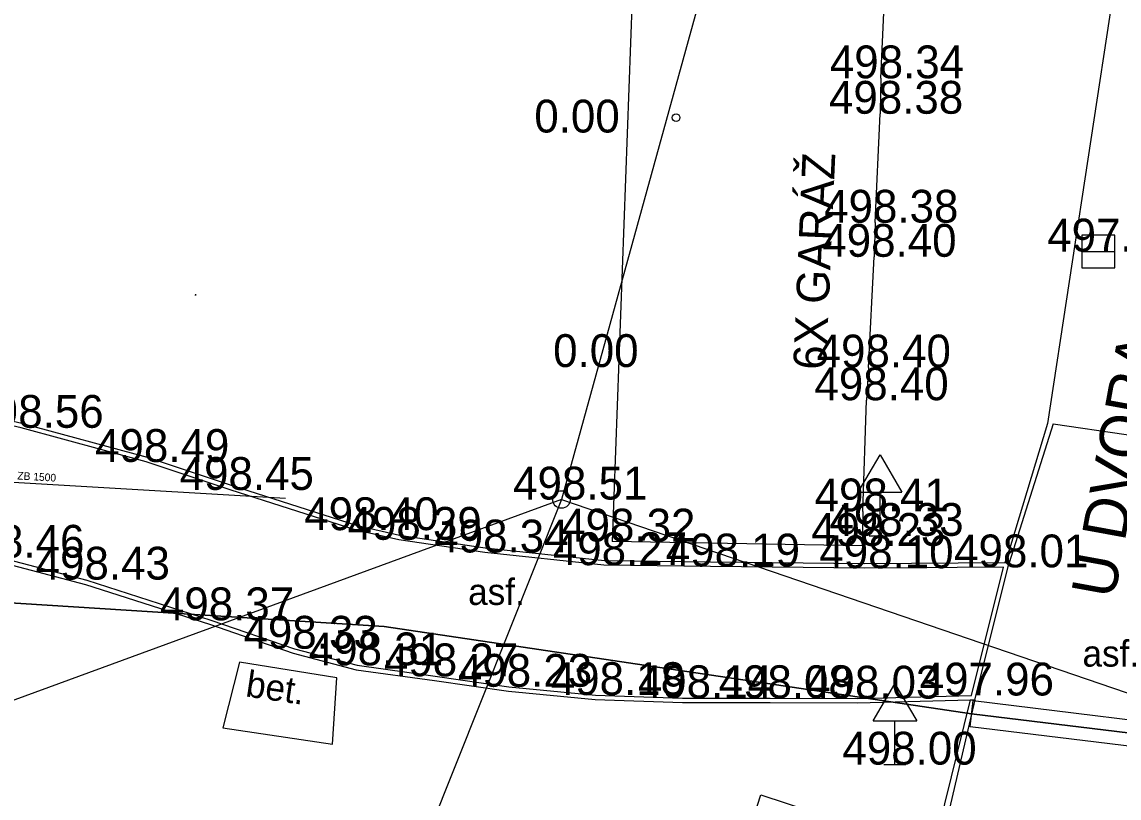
# Model space of a CAD drawing. Extents: x -669642 to -669119, y -1131006 to -1130466.
# Drawn here: x -669595.35 to -669570.28, y -1130617.18 to -1130599.43 of the extents above; entities that cross this region are included whole.
import ezdxf

# ---------------------------------------------------------------- set-up
doc = ezdxf.new("R2010")
doc.units = 0
for name, color, linetype in [('G_Bod_tecka', 7, 'Continuous'), ('G_Bod_vyska', 7, 'Continuous'), ('G_Budovy-znacky', 7, 'Continuous'), ('G_Budovy_Objekty', 7, 'Continuous'), ('G_Budovy_vstupy', 7, 'Continuous'), ('G_Cesty_Schody', 7, 'Continuous'), ('G_Objekty_dopravni', 7, 'Continuous'), ('G_Plochy_zpevnene', 7, 'Continuous'), ('G_Popisy_Nazvy', 7, 'Continuous'), ('G_Popisy_objektu', 7, 'Continuous'), ('G_Popisy_povrchu', 7, 'Continuous'), ('G_Site-kanalizace', 7, 'Continuous'), ('G_Site-Sloupy', 7, 'Continuous'), ('G_Vyskopis-bod_terenu', 7, 'Continuous'), ('G_Z_CHRANICKA-TEPLOVOD_kotovane', 7, 'Continuous'), ('G_Z_ELsilove_podz_kotovane', 7, 'Continuous'), ('G_Z_KANAL_podz_priblizne', 7, 'Continuous'), ('G_Z_SPOJE_nadz_kotovane', 7, 'Continuous'), ('G_Z_SPOJE_podz_kotovane', 7, 'Continuous'), ('Vrstva 17', 7, 'Continuous'), ('Vrstva 3', 7, 'Continuous')]:
    doc.layers.add(name, color=color, linetype=linetype)

msp = doc.modelspace()

# ---------------------------------------------------------------- linework, layer by layer
at = {"layer": 'G_Bod_tecka'}
for p, q in [((-669575.72, -1130600.72), (-669575.72, -1130600.72)), ((-669575.74, -1130601.53), (-669575.74, -1130601.53)), ((-669582.86, -1130601.96), (-669582.86, -1130601.96)), ((-669575.85, -1130604.02), (-669575.85, -1130604.02)), ((-669570.75, -1130604.68), (-669570.75, -1130604.68)), ((-669575.87, -1130604.8), (-669575.87, -1130604.8)), ((-669582.43, -1130607.32), (-669582.43, -1130607.32)), ((-669576, -1130607.33), (-669576, -1130607.33)), ((-669576.05, -1130608.08), (-669576.05, -1130608.08)), ((-669592.51, -1130609.49), (-669592.51, -1130609.49)), ((-669590.59, -1130610.13), (-669590.59, -1130610.13)), ((-669583.02, -1130610.35), (-669583.02, -1130610.35)), ((-669576.13, -1130610.62), (-669576.13, -1130610.62)), ((-669587.72, -1130611.05), (-669587.72, -1130611.05)), ((-669575.74, -1130611.18), (-669575.74, -1130611.18)), ((-669586.74, -1130611.27), (-669586.74, -1130611.27)), ((-669581.86, -1130611.31), (-669581.86, -1130611.31)), ((-669576.15, -1130611.41), (-669576.15, -1130611.41)), ((-669584.77, -1130611.56), (-669584.77, -1130611.56)), ((-669582.05, -1130611.85), (-669582.05, -1130611.85)), ((-669579.61, -1130611.88), (-669579.61, -1130611.88)), ((-669576.09, -1130611.92), (-669576.09, -1130611.92)), ((-669572.92, -1130611.9), (-669572.92, -1130611.9)), ((-669593.87, -1130612.18), (-669593.87, -1130612.18)), ((-669591.03, -1130613.11), (-669591.03, -1130613.11)), ((-669589.12, -1130613.76), (-669589.12, -1130613.76)), ((-669587.68, -1130614.14), (-669587.68, -1130614.14)), ((-669585.91, -1130614.39), (-669585.91, -1130614.39)), ((-669584.22, -1130614.63), (-669584.22, -1130614.63)), ((-669582.24, -1130614.82), (-669582.24, -1130614.82)), ((-669580.25, -1130614.89), (-669580.25, -1130614.89)), ((-669578.24, -1130614.89), (-669578.24, -1130614.89)), ((-669576.24, -1130614.9), (-669576.24, -1130614.9)), ((-669573.65, -1130614.83), (-669573.65, -1130614.83)), ((-669575.4, -1130616.41), (-669575.4, -1130616.41))]:
    msp.add_line(p, q, dxfattribs=at)
at = {"layer": 'G_Budovy-znacky'}
msp.add_circle((-669580.4, -1130601.62), 0.0875, dxfattribs=at)
at = {"layer": 'G_Budovy_Objekty'}
for p, q in [((-669581.1, -1130590.63), (-669581.86, -1130611.31)), ((-669575.72, -1130600.72), (-669575.74, -1130601.53)), ((-669575.85, -1130604.02), (-669575.87, -1130604.8)), ((-669576, -1130607.33), (-669576.05, -1130608.08)), ((-669576.13, -1130610.62), (-669576.15, -1130611.41)), ((-669576.15, -1130611.41), (-669581.86, -1130611.31))]:
    msp.add_line(p, q, dxfattribs=at)
at = {"layer": 'G_Budovy_vstupy'}
for points in [[(-669575.72, -1130600.72), (-669575.61, -1130598.22)], [(-669575.85, -1130604.02), (-669575.74, -1130601.53)], [(-669576, -1130607.33), (-669575.87, -1130604.8)], [(-669576.13, -1130610.62), (-669576.05, -1130608.08)]]:
    msp.add_lwpolyline(points, dxfattribs=at)
at = {"layer": 'G_Cesty_Schody'}
msp.add_line((-669571.78, -1130608.62), (-669572.79, -1130611.8), dxfattribs=at)
for points in [[(-669572.92, -1130611.9), (-669576.09, -1130611.92), (-669579.61, -1130611.88), (-669582.05, -1130611.85), (-669584.77, -1130611.56), (-669586.74, -1130611.27), (-669587.71, -1130611.05), (-669590.59, -1130610.13), (-669592.51, -1130609.49), (-669595.37, -1130608.71), (-669597.32, -1130608.26), (-669599.3, -1130608), (-669601.3, -1130607.84), (-669602.28, -1130607.79)], [(-669571.78, -1130608.62), (-669566.78, -1130609.35)], [(-669604.75, -1130610.71), (-669600.76, -1130610.87), (-669598.76, -1130611.07), (-669595.81, -1130611.68), (-669593.87, -1130612.19), (-669591.03, -1130613.11), (-669589.12, -1130613.76), (-669587.69, -1130614.14), (-669585.91, -1130614.39), (-669584.22, -1130614.63), (-669582.24, -1130614.82), (-669580.25, -1130614.89), (-669578.25, -1130614.89), (-669576.25, -1130614.9)], [(-669576.25, -1130614.9), (-669573.65, -1130614.83), (-669572.92, -1130611.9)], [(-669573.57, -1130614.93), (-669574.55, -1130619.11), (-669574.84, -1130620.09), (-669575.55, -1130621.43), (-669576.52, -1130622.62), (-669577.64, -1130623.57), (-669578.93, -1130624.28), (-669580.72, -1130624.98), (-669582.55, -1130625.4), (-669583.92, -1130625.42)]]:
    msp.add_lwpolyline(points, dxfattribs=at)
at = {"layer": 'G_Objekty_dopravni'}
for p, q in [((-669576.24, -1130610.18), (-669575.74, -1130609.33)), ((-669575.74, -1130609.33), (-669575.24, -1130610.18)), ((-669576.24, -1130610.18), (-669575.24, -1130610.18)), ((-669575.74, -1130611.18), (-669575.74, -1130610.18)), ((-669575.99, -1130611.18), (-669575.49, -1130611.18)), ((-669575.9, -1130615.41), (-669575.4, -1130614.56)), ((-669575.4, -1130614.56), (-669574.9, -1130615.41)), ((-669575.9, -1130615.41), (-669574.9, -1130615.41)), ((-669575.4, -1130616.41), (-669575.4, -1130615.41)), ((-669575.65, -1130616.41), (-669575.15, -1130616.41))]:
    msp.add_line(p, q, dxfattribs=at)
at = {"layer": 'G_Plochy_zpevnene'}
for p, q in [((-669570.32, -1130598.15), (-669571.91, -1130608.61)), ((-669572.79, -1130611.8), (-669572.89, -1130611.8)), ((-669576.25, -1130615), (-669573.68, -1130614.93))]:
    msp.add_line(p, q, dxfattribs=at)
for points in [[(-669572.89, -1130611.8), (-669576.09, -1130611.82), (-669579.61, -1130611.78), (-669582.04, -1130611.75), (-669584.76, -1130611.46), (-669586.72, -1130611.17), (-669587.68, -1130610.95), (-669590.56, -1130610.03), (-669592.48, -1130609.39), (-669595.35, -1130608.61), (-669597.3, -1130608.16), (-669599.29, -1130607.9), (-669601.29, -1130607.74), (-669602.28, -1130607.69)], [(-669571.91, -1130608.61), (-669572.76, -1130611.41), (-669572.89, -1130611.8)], [(-669604.75, -1130610.81), (-669600.77, -1130610.97), (-669598.78, -1130611.17), (-669595.83, -1130611.78), (-669593.9, -1130612.29), (-669591.06, -1130613.2), (-669589.15, -1130613.86), (-669587.71, -1130614.24), (-669585.92, -1130614.49), (-669584.23, -1130614.73), (-669582.25, -1130614.92), (-669580.25, -1130614.99), (-669578.25, -1130614.99), (-669576.25, -1130615)], [(-669573.68, -1130614.93), (-669573.57, -1130614.93), (-669572.79, -1130611.8)], [(-669590.38, -1130614.07), (-669590.76, -1130615.57), (-669588.25, -1130615.94), (-669588.15, -1130614.43), (-669590.38, -1130614.07)], [(-669573.68, -1130614.93), (-669574.7, -1130619.07), (-669574.98, -1130620.03), (-669575.68, -1130621.35), (-669576.62, -1130622.52), (-669577.73, -1130623.45), (-669578.99, -1130624.14), (-669580.76, -1130624.84), (-669582.57, -1130625.25), (-669583.93, -1130625.28)], [(-669578.46, -1130617.1), (-669576.19, -1130617.85), (-669576.97, -1130620.19), (-669577.68, -1130619.96), (-669579.53, -1130620.56), (-669579.6, -1130620.39), (-669579.78, -1130619.79), (-669579.81, -1130619.61), (-669579.91, -1130619.33), (-669579.11, -1130619.11), (-669578.46, -1130617.1)]]:
    msp.add_lwpolyline(points, dxfattribs=at)
at = {"layer": 'G_Site-kanalizace'}
msp.add_line((-669571.125, -1130604.68), (-669570.375, -1130604.68), dxfattribs=at)
msp.add_lwpolyline([(-669571.125, -1130605.054), (-669570.375, -1130605.054), (-669570.375, -1130604.304), (-669571.125, -1130604.304)], close=True, dxfattribs=at)
at = {"layer": 'G_Site-Sloupy'}
msp.add_circle((-669583.02, -1130610.35), 0.2, dxfattribs=at)
at = {"layer": 'G_Vyskopis-bod_terenu'}
for p, q in [((-669591.39, -1130605.67), (-669591.37, -1130605.67)), ((-669591.38, -1130605.655), (-669591.38, -1130605.67)), ((-669591.38, -1130605.685), (-669591.38, -1130605.67))]:
    msp.add_line(p, q, dxfattribs=at)
at = {"layer": 'G_Z_CHRANICKA-TEPLOVOD_kotovane'}
msp.add_lwpolyline([(-669573.61, -1130614.948), (-669567.536, -1130615.694), (-669567.609, -1130616.289), (-669573.683, -1130615.543)], close=True, dxfattribs=at)
at = {"layer": 'G_Z_ELsilove_podz_kotovane'}
msp.add_lwpolyline([(-669533.435, -1130619.583), (-669546.713, -1130618.107), (-669553.09, -1130617.456), (-669559.449, -1130616.694), (-669562.162, -1130616.208), (-669563.331, -1130616.419), (-669567.573, -1130615.992), (-669573.647, -1130615.246), (-669587.071, -1130613.252), (-669605.97, -1130612.055), (-669624.044, -1130611.379), (-669627.822, -1130609.92), (-669628.112, -1130609.531), (-669628.815, -1130608.586), (-669630.024, -1130606.962), (-669633.731, -1130597.833)], dxfattribs=at)
at = {"layer": 'G_Z_KANAL_podz_priblizne'}
msp.add_lwpolyline([(-669640.046, -1130607.343), (-669589.33, -1130610.32)], dxfattribs=at)
at = {"layer": 'G_Z_SPOJE_nadz_kotovane'}
for points in [[(-669574.46, -1130579.33), (-669583.02, -1130610.35)], [(-669583.02, -1130610.35), (-669626.87, -1130626.42)], [(-669583.02, -1130610.35), (-669592.14, -1130633.21)], [(-669583.02, -1130610.35), (-669556.92, -1130619.27)]]:
    msp.add_lwpolyline(points, dxfattribs=at)
at = {"layer": 'G_Z_SPOJE_podz_kotovane'}
for points in [[(-669640.046, -1130581.244), (-669639.749, -1130582.323), (-669639.644, -1130582.703), (-669639.089, -1130584.165), (-669638.73, -1130585.081), (-669638.721, -1130585.107), (-669638.47, -1130585.874), (-669638.285, -1130586.438), (-669637.848, -1130591.176), (-669633.731, -1130597.833), (-669630.024, -1130606.962), (-669627.822, -1130609.92), (-669624.044, -1130611.379), (-669605.97, -1130612.055), (-669587.071, -1130613.252), (-669573.647, -1130615.246), (-669567.573, -1130615.992), (-669563.331, -1130616.419), (-669562.162, -1130616.208), (-669559.449, -1130616.694), (-669553.09, -1130617.456), (-669548.523, -1130617.885), (-669533.435, -1130619.583)], [(-669640.046, -1130581.244), (-669639.763, -1130582.27), (-669639.644, -1130582.703), (-669639.089, -1130584.165), (-669638.73, -1130585.081), (-669638.721, -1130585.107), (-669638.47, -1130585.874), (-669638.285, -1130586.438), (-669637.848, -1130591.176), (-669633.731, -1130597.833), (-669630.024, -1130606.962), (-669627.822, -1130609.92), (-669624.044, -1130611.379), (-669605.97, -1130612.055), (-669587.071, -1130613.252), (-669573.647, -1130615.246), (-669567.573, -1130615.992), (-669563.331, -1130616.419), (-669562.162, -1130616.208), (-669559.449, -1130616.694), (-669553.09, -1130617.456), (-669548.523, -1130617.885), (-669533.435, -1130619.583)]]:
    msp.add_lwpolyline(points, dxfattribs=at)
at = {"layer": 'Vrstva 17'}
msp.add_lwpolyline([(-669640.046, -1130607.343), (-669589.33, -1130610.32)], dxfattribs=at)

# ---------------------------------------------------------------- texts
at = {"layer": 'G_Bod_vyska'}
for s, p in [('498.34', (-669576.886, -1130600.72)), ('498.38', (-669576.906, -1130601.53)), ('0.00', (-669583.64, -1130601.96)), ('498.38', (-669577.016, -1130604.02)), ('497.95', (-669571.918, -1130604.68)), ('498.40', (-669577.058, -1130604.8)), ('0.00', (-669583.21, -1130607.32)), ('498.40', (-669577.188, -1130607.33)), ('498.40', (-669577.238, -1130608.08)), ('498.56', (-669596.55, -1130608.71)), ('498.49', (-669593.678, -1130609.49)), ('498.45', (-669591.746, -1130610.13)), ('498.51', (-669584.124, -1130610.35)), ('498.41', (-669577.234, -1130610.62)), ('498.40', (-669588.898, -1130611.05)), ('498.33', (-669576.896, -1130611.18)), ('498.39', (-669587.908, -1130611.27)), ('498.32', (-669583.026, -1130611.31)), ('498.23', (-669577.313, -1130611.41)), ('498.46', (-669596.99, -1130611.68)), ('498.34', (-669585.926, -1130611.56)), ('498.27', (-669583.216, -1130611.85)), ('498.19', (-669580.636, -1130611.88)), ('498.10', (-669577.126, -1130611.92)), ('498.01', (-669574.046, -1130611.9)), ('498.43', (-669595.036, -1130612.18)), ('498.37', (-669592.196, -1130613.11)), ('498.33', (-669590.286, -1130613.76)), ('498.31', (-669588.794, -1130614.14)), ('498.27', (-669587.076, -1130614.39)), ('498.23', (-669585.386, -1130614.63)), ('498.18', (-669583.264, -1130614.82)), ('498.14', (-669581.274, -1130614.89)), ('498.08', (-669579.428, -1130614.89)), ('498.03', (-669577.428, -1130614.9)), ('497.96', (-669574.832, -1130614.83)), ('498.00', (-669576.599, -1130616.41))]:
    msp.add_text(s, height=0.75, dxfattribs=at).set_placement(p)
at = {"layer": 'G_Popisy_Nazvy'}
msp.add_text('U DVORA', height=1, rotation=79.6652, dxfattribs=at).set_placement((-669570.388, -1130612.644))
at = {"layer": 'G_Popisy_objektu'}
msp.add_text('6X GARÁŽ', height=0.75, rotation=87.5041, dxfattribs=at).set_placement((-669576.976, -1130607.395))
at = {"layer": 'G_Popisy_povrchu'}
for p in [(-669585.152, -1130612.76), (-669571.112, -1130614.17)]:
    msp.add_text('asf.', height=0.6, dxfattribs=at).set_placement(p)
msp.add_text('bet.', height=0.6, rotation=351.6144, dxfattribs=at).set_placement((-669590.258, -1130614.848))
at = {"layer": 'Vrstva 3'}
msp.add_text('ZB 1500', height=0.1755, rotation=356.6538, dxfattribs=at).set_placement((-669595.46, -1130609.89))

doc.saveas('drawing.dxf')
